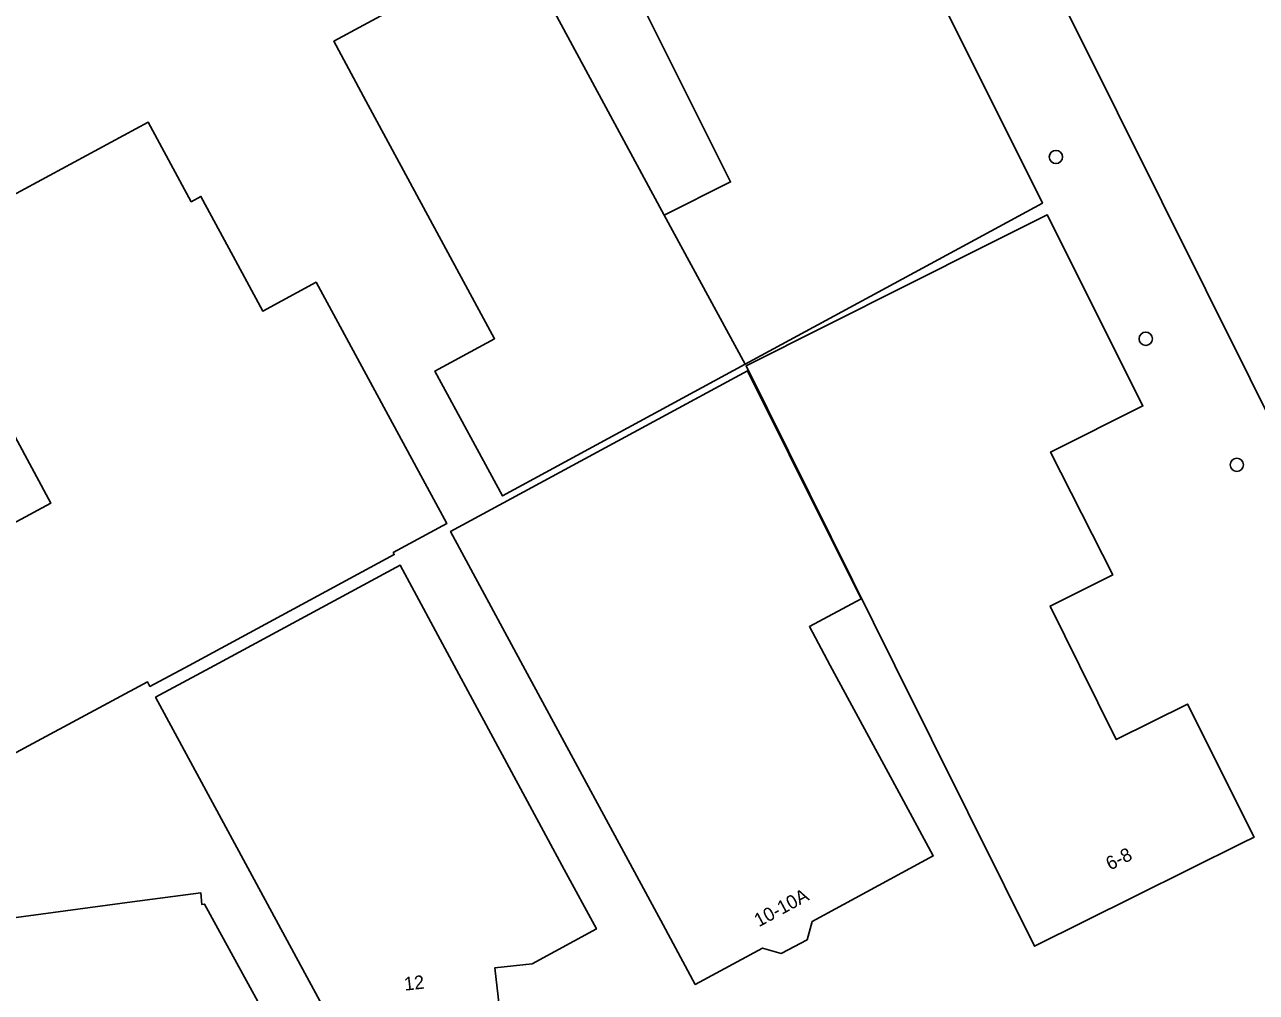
# Model space of a CAD drawing. Extents: x 158455 to 159797, y 387218 to 388672.
# Drawn here: x 158909.4 to 159000.4, y 387475.8 to 387547.3 of the extents above; entities that cross this region are included whole.
import ezdxf

# ---------------------------------------------------------------- set-up
doc = ezdxf.new("R2010")
doc.units = 0
for name, color, linetype in [('IMGEO_Boom', 7, 'Continuous'), ('IMGEO_Erf', 7, 'Continuous'), ('IMGEO_Pand', 7, 'Continuous'), ('IMGEO_Pand_nummerreeks', 7, 'Continuous')]:
    doc.layers.add(name, color=color, linetype=linetype)

msp = doc.modelspace()

# ---------------------------------------------------------------- linework, layer by layer
at = {"layer": 'IMGEO_Boom'}
for centre in [(158985.64, 387537.561), (158992.275, 387524.131), (158999.006, 387514.818)]:
    msp.add_circle(centre, 0.489, dxfattribs=at)
at = {"layer": 'IMGEO_Erf'}
for points in [[(158970.358, 387562.77), (158984.643, 387534.149), (158980.248, 387531.766), (158962.688, 387522.246), (158944.753, 387512.524), (158939.76, 387521.739), (158944.167, 387524.127), (158934.656, 387541.716), (158932.278, 387546.114), (158936.668, 387548.492)], [(158944.623, 387555.621), (158956.691, 387533.271), (158961.6, 387535.718), (158952.059, 387554.806)], [(159064.59, 387521.23), (159058.387, 387518.146), (159040.851, 387509.415), (159021.957, 387500), (159012.826, 387495.45), (159010.558, 387500), (159000, 387521.178), (158990.195, 387540.846), (158986.374, 387548.51)], [(158901.241, 387530.775), (158918.572, 387540.133), (158921.756, 387534.257), (158922.468, 387534.643), (158924.843, 387530.244), (158927.041, 387526.173), (158930.972, 387528.302), (158940.628, 387510.48), (158936.672, 387508.336), (158936.754, 387508.184), (158921.589, 387500), (158918.702, 387498.442), (158918.515, 387498.79), (158910.681, 387494.573), (158898.749, 387488.149)], [(158889.122, 387500), (158911.389, 387511.996), (158903.617, 387526.376)], [(158887.928, 387475.792), (158898, 387477.138), (158897.636, 387479.867), (158902.592, 387480.534), (158917.386, 387482.524), (158922.456, 387483.206), (158922.527, 387482.333), (158922.735, 387482.364), (158928.491, 387471.834), (158930.889, 387467.446)]]:
    msp.add_lwpolyline(points, dxfattribs=at)
for points in [[(159000.277, 387487.303), (158999.436, 387486.885), (158991.492, 387482.938), (158984.056, 387479.244), (158981.832, 387483.722), (158973.745, 387500), (158962.745, 387522.141), (158980.516, 387531.05), (158984.985, 387533.29), (158992.061, 387519.174), (158985.238, 387515.754), (158989.836, 387506.679), (158985.203, 387504.38), (158987.376, 387500), (158990.094, 387494.523), (158995.372, 387497.142)], [(158976.57, 387485.924), (158967.629, 387481.073), (158967.249, 387479.732), (158965.346, 387478.718), (158963.968, 387479.115), (158958.994, 387476.426), (158956.618, 387480.826), (158946.261, 387500), (158940.917, 387509.894), (158962.85, 387521.765), (158969.01, 387509.392), (158971.237, 387504.915), (158967.424, 387502.861), (158968.969, 387500), (158974.195, 387490.324)], [(158946.942, 387477.961), (158944.186, 387477.661), (158944.572, 387474.219), (158932.535, 387472.857), (158930.155, 387477.255), (158919.117, 387497.646), (158923.474, 387500), (158937.185, 387507.408), (158941.181, 387500), (158949.311, 387484.93), (158951.685, 387480.53)]]:
    msp.add_lwpolyline(points, close=True, dxfattribs=at)
at = {"layer": 'IMGEO_Pand'}
for points in [[(158968.455, 387566.688), (158964.251, 387564.592), (158960.613, 387571.916), (158954.312, 387568.777), (158953.678, 387566.859), (158952.931, 387566.476), (158956.09, 387560.157), (158956.386, 387560.305), (158957.728, 387557.622), (158952.059, 387554.806), (158961.6, 387535.718), (158956.691, 387533.271), (158962.688, 387522.246), (158980.248, 387531.766), (158984.643, 387534.149), (158970.358, 387562.77), (158969.322, 387564.904)], [(158956.691, 387533.271), (158944.623, 387555.621), (158938.442, 387552.28), (158938.894, 387551.445), (158936.397, 387550.104), (158935.945, 387550.939), (158935.479, 387550.673), (158936.668, 387548.492), (158932.278, 387546.114), (158934.656, 387541.716), (158944.167, 387524.127), (158939.76, 387521.739), (158944.753, 387512.524), (158962.688, 387522.246)], [(158984.056, 387479.244), (158991.492, 387482.938), (158999.436, 387486.885), (159000.277, 387487.303), (158995.372, 387497.142), (158990.094, 387494.523), (158987.376, 387500), (158985.203, 387504.38), (158989.836, 387506.679), (158985.238, 387515.754), (158992.061, 387519.174), (158984.985, 387533.29), (158980.516, 387531.05), (158962.745, 387522.141), (158973.745, 387500), (158981.832, 387483.722)], [(158968.969, 387500), (158967.424, 387502.861), (158971.237, 387504.915), (158969.01, 387509.392), (158962.85, 387521.765), (158940.917, 387509.894), (158946.261, 387500), (158956.618, 387480.826), (158958.994, 387476.426), (158963.968, 387479.115), (158965.346, 387478.718), (158967.249, 387479.732), (158967.629, 387481.073), (158976.57, 387485.924), (158974.195, 387490.324)], [(158930.155, 387477.255), (158932.535, 387472.857), (158944.572, 387474.219), (158944.186, 387477.661), (158946.942, 387477.961), (158951.685, 387480.53), (158949.311, 387484.93), (158941.181, 387500), (158937.185, 387507.408), (158923.474, 387500), (158919.117, 387497.646)]]:
    msp.add_lwpolyline(points, close=True, dxfattribs=at)
for points in [[(158986.374, 387548.51), (158990.195, 387540.846), (159000, 387521.178), (159010.558, 387500), (159012.826, 387495.45), (159021.957, 387500), (159040.851, 387509.415), (159058.387, 387518.146), (159035.885, 387563.273)], [(158898.749, 387488.149), (158910.681, 387494.573), (158918.515, 387498.79), (158918.702, 387498.442), (158921.589, 387500), (158936.754, 387508.184), (158936.672, 387508.336), (158940.628, 387510.48), (158930.972, 387528.302), (158927.041, 387526.173), (158924.843, 387530.244), (158922.468, 387534.643), (158921.756, 387534.257), (158918.572, 387540.133), (158901.241, 387530.775)], [(158903.617, 387526.376), (158911.389, 387511.996), (158889.122, 387500)], [(158895.408, 387462.651), (158901.178, 387463.425), (158901.123, 387463.789), (158899.932, 387463.646), (158899.801, 387464.599), (158923.909, 387467.857), (158924.084, 387466.503), (158930.889, 387467.446), (158928.491, 387471.834), (158922.735, 387482.364), (158922.527, 387482.333), (158922.456, 387483.206), (158917.386, 387482.524), (158902.592, 387480.534), (158897.636, 387479.867), (158898, 387477.138), (158887.928, 387475.792)]]:
    msp.add_lwpolyline(points, dxfattribs=at)

# ---------------------------------------------------------------- texts
at = {"layer": 'IMGEO_Pand_nummerreeks'}
for s, rotation, p in [('6-8', 26.41825, (158989.64, 387484.832)), ('10-10A', 28.48173, (158963.688, 387480.641)), ('12', 6.45563, (158937.536, 387475.96))]:
    msp.add_text(s, height=1, rotation=rotation, dxfattribs=at).set_placement(p)

doc.saveas('drawing.dxf')
